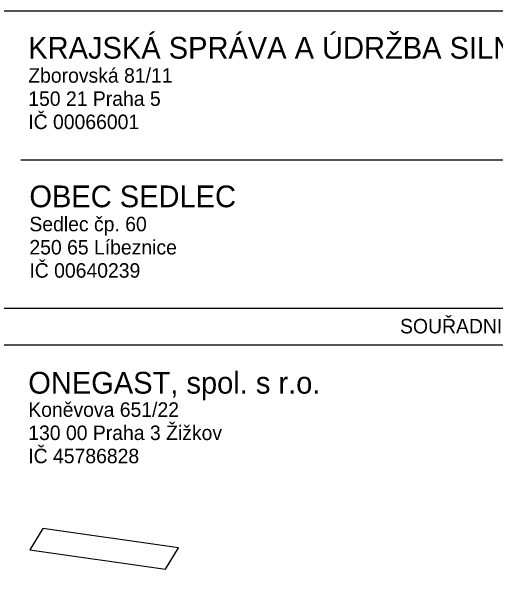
# Model space of a CAD drawing. Extents: x -740053 to -737481, y -1033516 to -1032488.
# Drawn here: x -737548.07 to -737514.63, y -1032916.58 to -1032877.51 of the extents above; entities that cross this region are included whole.
import ezdxf

# ---------------------------------------------------------------- set-up
doc = ezdxf.new("R2010")
doc.units = 0
for name, color, linetype in [('promika-rozp', 7, 'Continuous'), ('promika-rozp-text', 7, 'Continuous'), ('promika-rozp-text-firmy', 7, 'Continuous'), ('Vrstva 1', 7, 'Continuous')]:
    doc.layers.add(name, color=color, linetype=linetype)

msp = doc.modelspace()

# ---------------------------------------------------------------- linework, layer by layer
at = {"layer": 'promika-rozp'}
for points in [[(-737489.597, -1032887.762), (-737489.597, -1032877.512), (-737579.597, -1032877.512), (-737579.597, -1032887.762)], [(-737489.597, -1032887.762), (-737489.597, -1032898.012), (-737579.597, -1032898.012), (-737579.597, -1032887.762)], [(-737547.421, -1032887.762), (-737500.847, -1032887.762)], [(-737579.597, -1032921.012), (-737579.597, -1032900.512), (-737489.597, -1032900.512), (-737489.597, -1032921.012)]]:
    msp.add_lwpolyline(points, dxfattribs=at)
at = {"layer": 'Vrstva 1'}
msp.add_lwpolyline([(-737546.788, -1032914.67), (-737537.427, -1032915.997), (-737536.524, -1032914.514), (-737545.885, -1032913.187)], close=True, dxfattribs=at)

# ---------------------------------------------------------------- texts
at = {"layer": 'promika-rozp'}
msp.add_text('SOUŘADNICOVÝ SYSTÉM S-JTSK  VÝŠKOVÝ SYSTÉM Bpv', height=1, dxfattribs=at).set_placement((-737521.229, -1032899.73))
at = {"layer": 'promika-rozp-text'}
for s, height, p in [('ONEGAST, spol. s r.o.', 1.5, (-737546.901, -1032903.886)), ('Koněvova 651/22', 1, (-737546.901, -1032905.486)), ('130 00 Praha 3 Žižkov', 1, (-737546.901, -1032907.086)), ('IČ 45786828', 1, (-737546.901, -1032908.686))]:
    msp.add_text(s, height=height, dxfattribs=at).set_placement(p)
at = {"layer": 'promika-rozp-text-firmy'}
for s, height, p in [('KRAJSKÁ SPRÁVA A ÚDRŽBA SILNIC STŘEDOČESKÉHO KRAJE, P.O.', 1.5, (-737546.901, -1032880.777)), ('Zborovská 81/11', 1, (-737546.901, -1032882.436)), ('150 21 Praha 5', 1, (-737546.901, -1032884.036)), ('IČ 00066001', 1, (-737546.901, -1032885.636)), ('OBEC SEDLEC', 1.5, (-737546.823, -1032891.027)), ('Sedlec čp. 60', 1, (-737546.823, -1032892.686)), ('250 65 Líbeznice', 1, (-737546.823, -1032894.286)), ('IČ 00640239', 1, (-737546.823, -1032895.886))]:
    msp.add_text(s, height=height, dxfattribs=at).set_placement(p)

doc.saveas('drawing.dxf')
